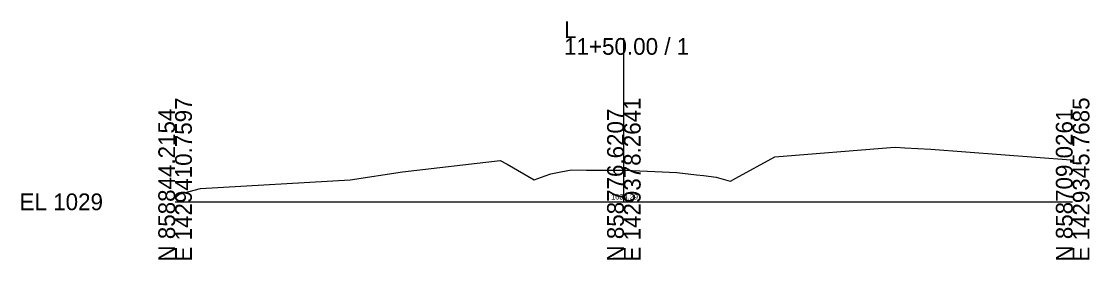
# Model space of a CAD drawing. Extents: x -26 to 153, y -10 to 13058.
# Drawn here: x -25.7 to 152.8, y -9.7 to 30.2 of the extents above; entities that cross this region are included whole.
import ezdxf

# ---------------------------------------------------------------- set-up
doc = ezdxf.new("R2010")
doc.units = 0
for name, color, linetype in [('Default', 7, 'Continuous'), ('Exist Cross Section Cell', 7, 'Continuous'), ('Exist XS Center Line Elevation Label', 7, 'Continuous'), ('Exist XS Ground Line', 7, 'Continuous')]:
    doc.layers.add(name, color=color, linetype=linetype)

msp = doc.modelspace()

# ---------------------------------------------------------------- linework, layer by layer
at = {"layer": 'Exist Cross Section Cell'}
for p, q in [((75, 0), (75, 27.44)), ((0, 0), (75, 0)), ((75, 0), (150, 0))]:
    msp.add_line(p, q, dxfattribs=at)
at = {"layer": 'Exist XS Ground Line'}
msp.add_lwpolyline([(0, 0.7), (0.66, 1.27), (4.26, 2.22), (29.28, 3.71), (37.98, 5.05), (54.3, 6.94), (55.52, 6.29), (60, 3.7), (61.85, 4.36), (62.79, 4.69), (64.49, 5.03), (66.24, 5.35), (68.78, 5.33), (75.24, 5.29), (81.38, 5.02), (83.84, 4.93), (87.13, 4.51), (88.28, 4.41), (90.43, 4.15), (92.39, 3.58), (92.8, 3.47), (93.73, 3.99), (100.25, 7.55), (119.58, 9.11), (120.44, 9.15), (121.96, 9.02), (126.29, 8.83), (149.69, 7.03), (150, 7)], dxfattribs=at)
msp.add_lwpolyline([(0, 0.7), (0.66, 1.27), (4.26, 2.22), (29.28, 3.71), (37.98, 5.05), (54.3, 6.94), (55.52, 6.29), (60, 3.7), (61.85, 4.36), (62.79, 4.69), (64.49, 5.03), (66.24, 5.35), (68.78, 5.33), (75.24, 5.29), (81.38, 5.02), (83.84, 4.93), (87.13, 4.51), (88.28, 4.41), (90.43, 4.15), (92.39, 3.58), (92.8, 3.47), (93.73, 3.99), (100.25, 7.55), (119.58, 9.11), (120.44, 9.15), (121.96, 9.02), (126.29, 8.83), (149.69, 7.03), (150, 7)], dxfattribs=at)
msp.add_lwpolyline([(0, 0.7), (0.66, 1.27), (4.26, 2.22), (29.28, 3.71), (37.98, 5.05), (54.3, 6.94), (55.52, 6.29), (60, 3.7), (61.85, 4.36), (62.79, 4.69), (64.49, 5.03), (66.24, 5.35), (68.78, 5.33), (75.24, 5.29), (81.38, 5.02), (83.84, 4.93), (87.13, 4.51), (88.28, 4.41), (90.43, 4.15), (92.39, 3.58), (92.8, 3.47), (93.73, 3.99), (100.25, 7.55), (119.58, 9.11), (120.44, 9.15), (121.96, 9.02), (126.29, 8.83), (149.69, 7.03), (150, 7)], dxfattribs=at)

# ---------------------------------------------------------------- texts
at = {"layer": 'Default'}
msp.add_text('-', height=0.0001, dxfattribs=at).set_placement((0, 0))
at = {"layer": 'Exist Cross Section Cell'}
for s, p in [('L', (65, 27.44)), ('11+50.00 / 1', (65, 24.64)), ('EL 1029', (-26, -1.4))]:
    msp.add_text(s, height=2.8, dxfattribs=at).set_placement(p)
for s, p in [('E 1429410.7597', (2.8, -10)), ('E 1429378.2641', (77.8, -10)), ('E 1429345.7685', (152.8, -10)), ('N 858844.2154', (0, -10)), ('N 858776.6207', (75, -10)), ('N 858709.0261', (150, -10))]:
    msp.add_text(s, height=2.8, rotation=90, dxfattribs=at).set_placement(p)
at = {"layer": 'Exist XS Center Line Elevation Label'}
msp.add_text('1034.29', height=0.9, dxfattribs=at).set_placement((72.86, 0.39))
msp.add_text('1034.29', height=0.9, dxfattribs=at).set_placement((72.86, 0.39))
msp.add_text('1034.29', height=0.9, dxfattribs=at).set_placement((72.86, 0.39))

doc.saveas('drawing.dxf')
